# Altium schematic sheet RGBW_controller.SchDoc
size A4; DrawnBy: Sergey Starovoitov; Revision: A; SheetNumber: 1; SheetTotal: 1
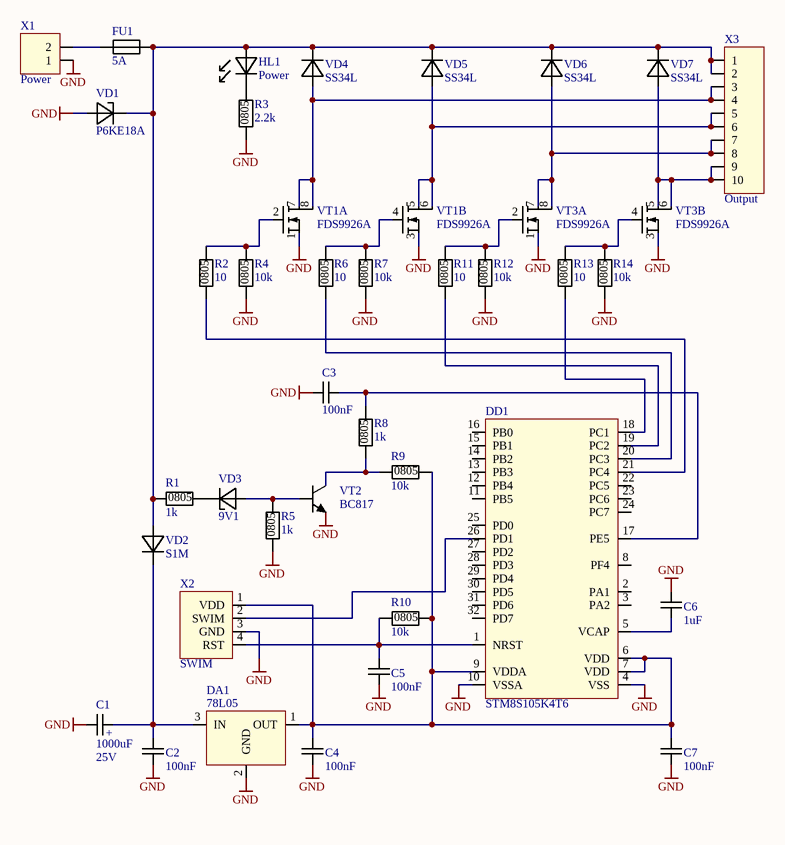
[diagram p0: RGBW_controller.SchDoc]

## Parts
C1  1000uF  Voltage: 25V  [CapEl 10x20x5 axial]
C2  100nF  [C0805]
C3  100nF  [C0805]
C4  100nF  [C0805]
C5  100nF  [C0805]
C6  1uF  [C0805]
C7  100nF  [C0805]
DA1  78L05  [TO92 line]
DD1  STM8S105K4T6  [TQFP32]
FU1  5A  [Fuse 4x10]
HL1  Power  [LED 3mm green]
R1  1k  [R0805]
R2  10  [R0805]
R3  2.2k  [R0805]
R4  10k  [R0805]
R5  1k  [R0805]
R6  10  [R0805]
R7  10k  [R0805]
R8  1k  [R0805]
R9  10k  [R0805]
R10  10k  [R0805]
R11  10  [R0805]
R12  10k  [R0805]
R13  10  [R0805]
R14  10k  [R0805]
VD1  P6KE18A  [DO15]
VD2  S1M  [SMA]
VD3  9V1  [SOD80]
VD4  SS34L  [SMA]
VD5  SS34L  [SMA]
VD6  SS34L  [SMA]
VD7  SS34L  [SMA]
VT1  FDS9926A  [SO8]  (parts A,B of 2)
VT2  BC817  [SOT23-3]
VT3  FDS9926A  [SO8]  (parts A,B of 2)
X1  Power  [DG301-5,0-2P]
X2  SWIM  [PLS4]
X3  Output  [DG380-3,81-10P]

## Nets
GND: C1.2 C2.2 C3.2 C4.2 C5.1 C6.2 C7.1 DA1.2(GND) DD1.4(VSS) DD1.10(VSSA) R3.1 R4.1 R5.1 R7.1 R12.1 R14.1 VD1.1(A) VT1.1(S) VT1.3(S) VT2.2(E) VT3.1(S) VT3.3(S) X1.1 X2.3(GND)
NetC1_1: C1.1 C2.1 DA1.3(IN) VD2.2(K)
NetC3_1: C3.1 DD1.17(PE5) R8.2
NetC4_1: C4.1 C7.2 DA1.1(OUT) DD1.6(VDD) DD1.7(VDD) DD1.9(VDDA) R9.2 R10.2 X2.1(VDD)
NetC5_2: C5.2 DD1.1(NRST) R10.1 X2.4(RST)
NetC6_1: C6.1 DD1.5(VCAP)
NetDD1_18: DD1.18(PC1) R13.1
NetDD1_19: DD1.19(PC2) R11.1
NetDD1_20: DD1.20(PC3) R6.1
NetDD1_21: DD1.21(PC4) R2.1
NetDD1_26: DD1.26(PD1) X2.2(SWIM)
NetFU1_1: FU1.1 X1.2
NetFU1_2: FU1.2 HL1.1(A) R1.1 VD1.2(K) VD2.1(A) VD4.2(K) VD5.2(K) VD6.2(K) VD7.2(K) X3.1 X3.2
NetHL1_2: HL1.2(K) R3.2
NetR1_2: R1.2 VD3.2(K)
NetR2_2: R2.2 R4.2 VT1.2(G)
NetR5_2: R5.2 VD3.1(A) VT2.1(B)
NetR6_2: R6.2 R7.2 VT1.4(G)
NetR8_1: R8.1 R9.1 VT2.3(C)
NetR11_2: R11.2 R12.2 VT3.2(G)
NetR13_2: R13.2 R14.2 VT3.4(G)
NetVD4_1: VD4.1(A) VT1.7(D1) VT1.8(D2) X3.3 X3.4
NetVD5_1: VD5.1(A) VT1.5(D1) VT1.6(D2) X3.5 X3.6
NetVD6_1: VD6.1(A) VT3.7(D1) VT3.8(D2) X3.7 X3.8
NetVD7_1: VD7.1(A) VT3.5(D1) VT3.6(D2) X3.9 X3.10

Not connected (* = marked no-connect by the designer): DD1 2(PA1) 3(PA2) 8(PF4) 11(PB5) 12(PB4) 13(PB3) 14(PB2) 15(PB1) 16(PB0) 22(PC5) 23(PC6) 24(PC7) 25(PD0) 27(PD2) 28(PD3) 29(PD4) 30(PD5) 31(PD6) 32(PD7)

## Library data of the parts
C1 = CapEL_10x20x5_axial: Electrolytic capacitor
C2-C7 = C0805: 0805 SMD capacitors
DA1 = L78L: Positive Linear Voltage Regulator; Part Number: L78L
DD1 = STM8S105K4T6: STM8 MCU with 16kB Flash
FU1 = Fuse_4x10: PCB Leaded Fuse 4x10 15mm pitch
HL1 = LED 3mm green: 3mm DIP green LED
R1-R14 = R0805: 0805 SMD 1/8W resistor
VD1 = P6KE18A: 18V 600W THT Unidirectional Supressor
VD2 = S1M: 1A Surface Mount Rectifier
VD3 = BZV55: 500mW SMD Zener Diode; Part Number: BZV55
VD4-VD7 = SS34L: 3A Low Case Schottky Barrier Diode
VT1 VT3 = FDS9926A: Dual 20V 6.5A SO8 SMD n-MOSFET transistor with Rds=30mOhm
VT2 = BC817: 45V 500mA SOT23-3 SMD NPN transistor with h21>100
X1 = DG301-5,0-2P: 2 pin Screw Terminal PCB Block
X2 = SWIM: 4 pin SWIM connector for STM8 MCU programming
X3 = DG380-3,81-10P: 10 pin Screw Terminal PCB Block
